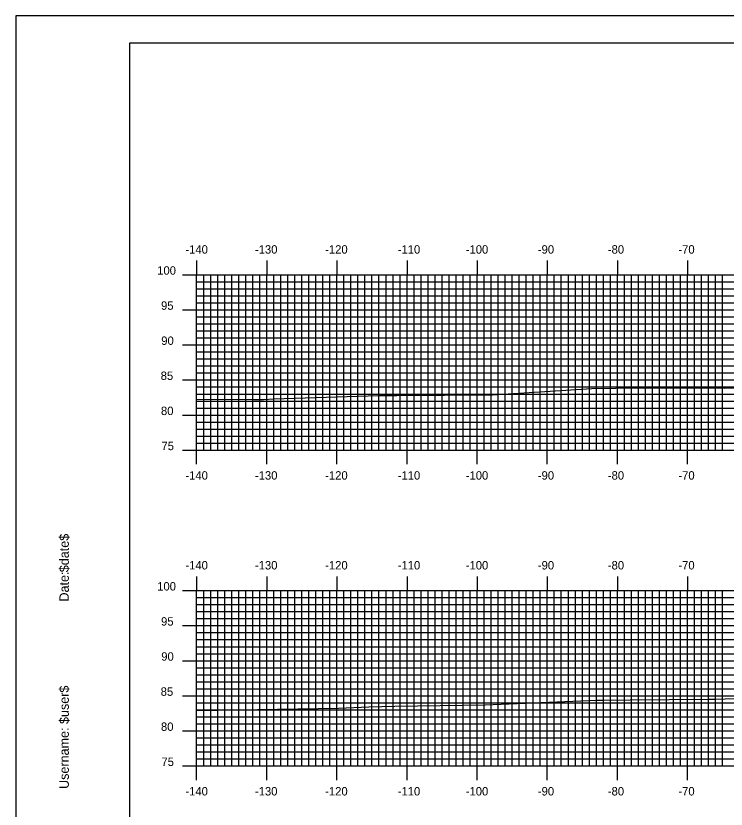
# Model space of a CAD drawing. Extents: x 1666 to 2009, y -1658 to -1438.
# Drawn here: x 1665.9 to 1767.2, y -1550.7 to -1437.7 of the extents above; entities that cross this region are included whole.
import ezdxf

# ---------------------------------------------------------------- set-up
doc = ezdxf.new("R2010")
doc.units = 0
for name, color, linetype in [('BORDER', 7, 'Continuous'), ('H_V ANNOTATION', 7, 'Continuous'), ('MAJOR', 7, 'Continuous'), ('MINOR', 7, 'Continuous'), ('PLOT BOUNDARY', 7, 'Continuous'), ('S_Roadway_Centerline', 7, 'Continuous')]:
    doc.layers.add(name, color=color, linetype=linetype)

msp = doc.modelspace()

# ---------------------------------------------------------------- linework, layer by layer
at = {"layer": 'BORDER'}
msp.add_lwpolyline([(1682.07, -1651.6), (2002.07, -1651.6), (2002.07, -1441.6), (1682.07, -1441.6)], close=True, dxfattribs=at)
at = {"layer": 'MAJOR'}
for p, q in [((1691.67, -1472.6), (1691.67, -1474.6)), ((1701.67, -1472.6), (1701.67, -1474.6)), ((1711.67, -1472.6), (1711.67, -1474.6)), ((1721.67, -1472.6), (1721.67, -1474.6)), ((1731.67, -1472.6), (1731.67, -1474.6)), ((1741.67, -1472.6), (1741.67, -1474.6)), ((1751.67, -1472.6), (1751.67, -1474.6)), ((1761.67, -1472.6), (1761.67, -1474.6)), ((1689.67, -1474.6), (1691.67, -1474.6)), ((1691.67, -1474.6), (1971.67, -1474.6)), ((1691.67, -1499.6), (1691.67, -1474.6)), ((1691.67, -1499.6), (1691.67, -1474.6)), ((1691.67, -1474.6), (1971.67, -1474.6)), ((1701.67, -1499.6), (1701.67, -1474.6)), ((1711.67, -1499.6), (1711.67, -1474.6)), ((1721.67, -1499.6), (1721.67, -1474.6)), ((1731.67, -1499.6), (1731.67, -1474.6)), ((1741.67, -1499.6), (1741.67, -1474.6)), ((1751.67, -1499.6), (1751.67, -1474.6)), ((1761.67, -1499.6), (1761.67, -1474.6)), ((1689.67, -1479.6), (1691.67, -1479.6)), ((1691.67, -1479.6), (1971.67, -1479.6)), ((1689.67, -1484.6), (1691.67, -1484.6)), ((1691.67, -1484.6), (1971.67, -1484.6)), ((1689.67, -1489.6), (1691.67, -1489.6)), ((1691.67, -1489.6), (1971.67, -1489.6)), ((1689.67, -1494.6), (1691.67, -1494.6)), ((1691.67, -1494.6), (1971.67, -1494.6)), ((1689.67, -1499.6), (1691.67, -1499.6)), ((1691.67, -1499.6), (1971.67, -1499.6)), ((1691.67, -1499.6), (1971.67, -1499.6)), ((1691.67, -1501.61), (1691.67, -1499.6)), ((1701.67, -1501.61), (1701.67, -1499.6)), ((1711.67, -1501.61), (1711.67, -1499.6)), ((1721.67, -1501.61), (1721.67, -1499.6)), ((1731.67, -1501.61), (1731.67, -1499.6)), ((1741.67, -1501.61), (1741.67, -1499.6)), ((1751.67, -1501.61), (1751.67, -1499.6)), ((1761.67, -1501.61), (1761.67, -1499.6)), ((1691.67, -1517.6), (1691.67, -1519.6)), ((1701.67, -1517.6), (1701.67, -1519.6)), ((1711.67, -1517.6), (1711.67, -1519.6)), ((1721.67, -1517.6), (1721.67, -1519.6)), ((1731.67, -1517.6), (1731.67, -1519.6)), ((1741.67, -1517.6), (1741.67, -1519.6)), ((1751.67, -1517.6), (1751.67, -1519.6)), ((1761.67, -1517.6), (1761.67, -1519.6)), ((1689.67, -1519.6), (1691.67, -1519.6)), ((1691.67, -1519.6), (1971.67, -1519.6)), ((1691.67, -1544.6), (1691.67, -1519.6)), ((1691.67, -1544.6), (1691.67, -1519.6)), ((1691.67, -1519.6), (1971.67, -1519.6)), ((1701.67, -1544.6), (1701.67, -1519.6)), ((1711.67, -1544.6), (1711.67, -1519.6)), ((1721.67, -1544.6), (1721.67, -1519.6)), ((1731.67, -1544.6), (1731.67, -1519.6)), ((1741.67, -1544.6), (1741.67, -1519.6)), ((1751.67, -1544.6), (1751.67, -1519.6)), ((1761.67, -1544.6), (1761.67, -1519.6)), ((1689.67, -1524.6), (1691.67, -1524.6)), ((1691.67, -1524.6), (1971.67, -1524.6)), ((1689.67, -1529.6), (1691.67, -1529.6)), ((1691.67, -1529.6), (1971.67, -1529.6)), ((1689.67, -1534.6), (1691.67, -1534.6)), ((1691.67, -1534.6), (1971.67, -1534.6)), ((1689.67, -1539.6), (1691.67, -1539.6)), ((1691.67, -1539.6), (1971.67, -1539.6)), ((1689.67, -1544.6), (1691.67, -1544.6)), ((1691.67, -1544.6), (1971.67, -1544.6)), ((1691.67, -1544.6), (1971.67, -1544.6)), ((1691.67, -1546.61), (1691.67, -1544.6)), ((1701.67, -1546.61), (1701.67, -1544.6)), ((1711.67, -1546.61), (1711.67, -1544.6)), ((1721.67, -1546.61), (1721.67, -1544.6)), ((1731.67, -1546.61), (1731.67, -1544.6)), ((1741.67, -1546.61), (1741.67, -1544.6)), ((1751.67, -1546.61), (1751.67, -1544.6)), ((1761.67, -1546.61), (1761.67, -1544.6))]:
    msp.add_line(p, q, dxfattribs=at)
at = {"layer": 'MINOR'}
for p, q in [((1692.67, -1499.6), (1692.67, -1474.6)), ((1693.67, -1499.6), (1693.67, -1474.6)), ((1694.67, -1499.6), (1694.67, -1474.6)), ((1695.67, -1499.6), (1695.67, -1474.6)), ((1696.67, -1499.6), (1696.67, -1474.6)), ((1697.67, -1499.6), (1697.67, -1474.6)), ((1698.67, -1499.6), (1698.67, -1474.6)), ((1699.67, -1499.6), (1699.67, -1474.6)), ((1700.67, -1499.6), (1700.67, -1474.6)), ((1702.67, -1499.6), (1702.67, -1474.6)), ((1703.67, -1499.6), (1703.67, -1474.6)), ((1704.67, -1499.6), (1704.67, -1474.6)), ((1705.67, -1499.6), (1705.67, -1474.6)), ((1706.67, -1499.6), (1706.67, -1474.6)), ((1707.67, -1499.6), (1707.67, -1474.6)), ((1708.67, -1499.6), (1708.67, -1474.6)), ((1709.67, -1499.6), (1709.67, -1474.6)), ((1710.67, -1499.6), (1710.67, -1474.6)), ((1712.67, -1499.6), (1712.67, -1474.6)), ((1713.67, -1499.6), (1713.67, -1474.6)), ((1714.67, -1499.6), (1714.67, -1474.6)), ((1715.67, -1499.6), (1715.67, -1474.6)), ((1716.67, -1499.6), (1716.67, -1474.6)), ((1717.67, -1499.6), (1717.67, -1474.6)), ((1718.67, -1499.6), (1718.67, -1474.6)), ((1719.67, -1499.6), (1719.67, -1474.6)), ((1720.67, -1499.6), (1720.67, -1474.6)), ((1722.67, -1499.6), (1722.67, -1474.6)), ((1723.67, -1499.6), (1723.67, -1474.6)), ((1724.67, -1499.6), (1724.67, -1474.6)), ((1725.67, -1499.6), (1725.67, -1474.6)), ((1726.67, -1499.6), (1726.67, -1474.6)), ((1727.67, -1499.6), (1727.67, -1474.6)), ((1728.67, -1499.6), (1728.67, -1474.6)), ((1729.67, -1499.6), (1729.67, -1474.6)), ((1730.67, -1499.6), (1730.67, -1474.6)), ((1732.67, -1499.6), (1732.67, -1474.6)), ((1733.67, -1499.6), (1733.67, -1474.6)), ((1734.67, -1499.6), (1734.67, -1474.6)), ((1735.67, -1499.6), (1735.67, -1474.6)), ((1736.67, -1499.6), (1736.67, -1474.6)), ((1737.67, -1499.6), (1737.67, -1474.6)), ((1738.67, -1499.6), (1738.67, -1474.6)), ((1739.67, -1499.6), (1739.67, -1474.6)), ((1740.67, -1499.6), (1740.67, -1474.6)), ((1742.67, -1499.6), (1742.67, -1474.6)), ((1743.67, -1499.6), (1743.67, -1474.6)), ((1744.67, -1499.6), (1744.67, -1474.6)), ((1745.67, -1499.6), (1745.67, -1474.6)), ((1746.67, -1499.6), (1746.67, -1474.6)), ((1747.67, -1499.6), (1747.67, -1474.6)), ((1748.67, -1499.6), (1748.67, -1474.6)), ((1749.67, -1499.6), (1749.67, -1474.6)), ((1750.67, -1499.6), (1750.67, -1474.6)), ((1752.67, -1499.6), (1752.67, -1474.6)), ((1753.67, -1499.6), (1753.67, -1474.6)), ((1754.67, -1499.6), (1754.67, -1474.6)), ((1755.67, -1499.6), (1755.67, -1474.6)), ((1756.67, -1499.6), (1756.67, -1474.6)), ((1757.67, -1499.6), (1757.67, -1474.6)), ((1758.67, -1499.6), (1758.67, -1474.6)), ((1759.67, -1499.6), (1759.67, -1474.6)), ((1760.67, -1499.6), (1760.67, -1474.6)), ((1762.67, -1499.6), (1762.67, -1474.6)), ((1763.67, -1499.6), (1763.67, -1474.6)), ((1764.67, -1499.6), (1764.67, -1474.6)), ((1765.67, -1499.6), (1765.67, -1474.6)), ((1766.67, -1499.6), (1766.67, -1474.6)), ((1691.67, -1475.6), (1971.67, -1475.6)), ((1691.67, -1475.6), (1693.68, -1475.6)), ((1691.67, -1476.6), (1971.67, -1476.6)), ((1691.67, -1476.6), (1693.68, -1476.6)), ((1691.67, -1477.6), (1971.67, -1477.6)), ((1691.67, -1477.6), (1693.68, -1477.6)), ((1691.67, -1478.6), (1971.67, -1478.6)), ((1691.67, -1478.6), (1693.68, -1478.6)), ((1691.67, -1480.6), (1971.67, -1480.6)), ((1691.67, -1480.6), (1693.68, -1480.6)), ((1691.67, -1481.6), (1971.67, -1481.6)), ((1691.67, -1481.6), (1693.68, -1481.6)), ((1691.67, -1482.6), (1971.67, -1482.6)), ((1691.67, -1482.6), (1693.68, -1482.6)), ((1691.67, -1483.6), (1971.67, -1483.6)), ((1691.67, -1483.6), (1693.68, -1483.6)), ((1691.67, -1485.6), (1971.67, -1485.6)), ((1691.67, -1485.6), (1693.68, -1485.6)), ((1691.67, -1486.6), (1971.67, -1486.6)), ((1691.67, -1486.6), (1693.68, -1486.6)), ((1691.67, -1487.6), (1971.67, -1487.6)), ((1691.67, -1487.6), (1693.68, -1487.6)), ((1691.67, -1488.6), (1971.67, -1488.6)), ((1691.67, -1488.6), (1693.68, -1488.6)), ((1691.67, -1490.6), (1971.67, -1490.6)), ((1691.67, -1490.6), (1693.68, -1490.6)), ((1691.67, -1491.6), (1971.67, -1491.6)), ((1691.67, -1491.6), (1693.68, -1491.6)), ((1691.67, -1492.6), (1971.67, -1492.6)), ((1691.67, -1492.6), (1693.68, -1492.6)), ((1691.67, -1493.6), (1971.67, -1493.6)), ((1691.67, -1493.6), (1693.68, -1493.6)), ((1691.67, -1495.6), (1971.67, -1495.6)), ((1691.67, -1495.6), (1693.68, -1495.6)), ((1691.67, -1496.6), (1971.67, -1496.6)), ((1691.67, -1496.6), (1693.68, -1496.6)), ((1691.67, -1497.6), (1971.67, -1497.6)), ((1691.67, -1497.6), (1693.68, -1497.6)), ((1691.67, -1498.6), (1971.67, -1498.6)), ((1691.67, -1498.6), (1693.68, -1498.6)), ((1692.67, -1544.6), (1692.67, -1519.6)), ((1693.67, -1544.6), (1693.67, -1519.6)), ((1694.67, -1544.6), (1694.67, -1519.6)), ((1695.67, -1544.6), (1695.67, -1519.6)), ((1696.67, -1544.6), (1696.67, -1519.6)), ((1697.67, -1544.6), (1697.67, -1519.6)), ((1698.67, -1544.6), (1698.67, -1519.6)), ((1699.67, -1544.6), (1699.67, -1519.6)), ((1700.67, -1544.6), (1700.67, -1519.6)), ((1702.67, -1544.6), (1702.67, -1519.6)), ((1703.67, -1544.6), (1703.67, -1519.6)), ((1704.67, -1544.6), (1704.67, -1519.6)), ((1705.67, -1544.6), (1705.67, -1519.6)), ((1706.67, -1544.6), (1706.67, -1519.6)), ((1707.67, -1544.6), (1707.67, -1519.6)), ((1708.67, -1544.6), (1708.67, -1519.6)), ((1709.67, -1544.6), (1709.67, -1519.6)), ((1710.67, -1544.6), (1710.67, -1519.6)), ((1712.67, -1544.6), (1712.67, -1519.6)), ((1713.67, -1544.6), (1713.67, -1519.6)), ((1714.67, -1544.6), (1714.67, -1519.6)), ((1715.67, -1544.6), (1715.67, -1519.6)), ((1716.67, -1544.6), (1716.67, -1519.6)), ((1717.67, -1544.6), (1717.67, -1519.6)), ((1718.67, -1544.6), (1718.67, -1519.6)), ((1719.67, -1544.6), (1719.67, -1519.6)), ((1720.67, -1544.6), (1720.67, -1519.6)), ((1722.67, -1544.6), (1722.67, -1519.6)), ((1723.67, -1544.6), (1723.67, -1519.6)), ((1724.67, -1544.6), (1724.67, -1519.6)), ((1725.67, -1544.6), (1725.67, -1519.6)), ((1726.67, -1544.6), (1726.67, -1519.6)), ((1727.67, -1544.6), (1727.67, -1519.6)), ((1728.67, -1544.6), (1728.67, -1519.6)), ((1729.67, -1544.6), (1729.67, -1519.6)), ((1730.67, -1544.6), (1730.67, -1519.6)), ((1732.67, -1544.6), (1732.67, -1519.6)), ((1733.67, -1544.6), (1733.67, -1519.6)), ((1734.67, -1544.6), (1734.67, -1519.6)), ((1735.67, -1544.6), (1735.67, -1519.6)), ((1736.67, -1544.6), (1736.67, -1519.6)), ((1737.67, -1544.6), (1737.67, -1519.6)), ((1738.67, -1544.6), (1738.67, -1519.6)), ((1739.67, -1544.6), (1739.67, -1519.6)), ((1740.67, -1544.6), (1740.67, -1519.6)), ((1742.67, -1544.6), (1742.67, -1519.6)), ((1743.67, -1544.6), (1743.67, -1519.6)), ((1744.67, -1544.6), (1744.67, -1519.6)), ((1745.67, -1544.6), (1745.67, -1519.6)), ((1746.67, -1544.6), (1746.67, -1519.6)), ((1747.67, -1544.6), (1747.67, -1519.6)), ((1748.67, -1544.6), (1748.67, -1519.6)), ((1749.67, -1544.6), (1749.67, -1519.6)), ((1750.67, -1544.6), (1750.67, -1519.6)), ((1752.67, -1544.6), (1752.67, -1519.6)), ((1753.67, -1544.6), (1753.67, -1519.6)), ((1754.67, -1544.6), (1754.67, -1519.6)), ((1755.67, -1544.6), (1755.67, -1519.6)), ((1756.67, -1544.6), (1756.67, -1519.6)), ((1757.67, -1544.6), (1757.67, -1519.6)), ((1758.67, -1544.6), (1758.67, -1519.6)), ((1759.67, -1544.6), (1759.67, -1519.6)), ((1760.67, -1544.6), (1760.67, -1519.6)), ((1762.67, -1544.6), (1762.67, -1519.6)), ((1763.67, -1544.6), (1763.67, -1519.6)), ((1764.67, -1544.6), (1764.67, -1519.6)), ((1765.67, -1544.6), (1765.67, -1519.6)), ((1766.67, -1544.6), (1766.67, -1519.6)), ((1691.67, -1520.6), (1971.67, -1520.6)), ((1691.67, -1520.6), (1693.68, -1520.6)), ((1691.67, -1521.6), (1971.67, -1521.6)), ((1691.67, -1521.6), (1693.68, -1521.6)), ((1691.67, -1522.6), (1971.67, -1522.6)), ((1691.67, -1522.6), (1693.68, -1522.6)), ((1691.67, -1523.6), (1971.67, -1523.6)), ((1691.67, -1523.6), (1693.68, -1523.6)), ((1691.67, -1525.6), (1971.67, -1525.6)), ((1691.67, -1525.6), (1693.68, -1525.6)), ((1691.67, -1526.6), (1971.67, -1526.6)), ((1691.67, -1526.6), (1693.68, -1526.6)), ((1691.67, -1527.6), (1971.67, -1527.6)), ((1691.67, -1527.6), (1693.68, -1527.6)), ((1691.67, -1528.6), (1971.67, -1528.6)), ((1691.67, -1528.6), (1693.68, -1528.6)), ((1691.67, -1530.6), (1971.67, -1530.6)), ((1691.67, -1530.6), (1693.68, -1530.6)), ((1691.67, -1531.6), (1971.67, -1531.6)), ((1691.67, -1531.6), (1693.68, -1531.6)), ((1691.67, -1532.6), (1971.67, -1532.6)), ((1691.67, -1532.6), (1693.68, -1532.6)), ((1691.67, -1533.6), (1971.67, -1533.6)), ((1691.67, -1533.6), (1693.68, -1533.6)), ((1691.67, -1535.6), (1971.67, -1535.6)), ((1691.67, -1535.6), (1693.68, -1535.6)), ((1691.67, -1536.6), (1971.67, -1536.6)), ((1691.67, -1536.6), (1693.68, -1536.6)), ((1691.67, -1537.6), (1971.67, -1537.6)), ((1691.67, -1537.6), (1693.68, -1537.6)), ((1691.67, -1538.6), (1971.67, -1538.6)), ((1691.67, -1538.6), (1693.68, -1538.6)), ((1691.67, -1540.6), (1971.67, -1540.6)), ((1691.67, -1540.6), (1693.68, -1540.6)), ((1691.67, -1541.6), (1971.67, -1541.6)), ((1691.67, -1541.6), (1693.68, -1541.6)), ((1691.67, -1542.6), (1971.67, -1542.6)), ((1691.67, -1542.6), (1693.68, -1542.6)), ((1691.67, -1543.6), (1971.67, -1543.6)), ((1691.67, -1543.6), (1693.68, -1543.6))]:
    msp.add_line(p, q, dxfattribs=at)
at = {"layer": 'PLOT BOUNDARY'}
msp.add_lwpolyline([(1665.89, -1657.72), (2005.89, -1657.72), (2005.89, -1437.72), (1665.89, -1437.72)], close=True, dxfattribs=at)
at = {"layer": 'S_Roadway_Centerline'}
for points in [[(1691.67, -1492.34), (1699.81, -1492.38), (1701.19, -1492.36), (1702.67, -1492.28), (1717.58, -1491.83), (1720.22, -1491.81), (1733.87, -1491.74), (1748.02, -1490.83), (1751.46, -1490.79), (1754.73, -1490.74), (1766.98, -1490.75), (1771.61, -1490.61), (1783.49, -1489.99), (1789.56, -1489.78), (1809.24, -1489.53), (1816.75, -1489.54), (1824.44, -1489.13), (1833.5, -1489.1), (1841.83, -1489.15), (1848.09, -1488.88), (1855.96, -1488.91), (1865.49, -1488.85), (1876.3, -1488.74)], [(1691.67, -1536.67), (1711.89, -1536.34), (1716.2, -1536.19), (1719.95, -1536.08), (1732.83, -1535.88), (1748.72, -1535.24), (1749.56, -1535.21), (1753.49, -1535.18), (1764.64, -1535.1), (1765.63, -1535.07), (1779.94, -1534.59), (1782.5, -1534.5), (1785.63, -1534.41), (1798.54, -1534.19), (1803.32, -1534.13), (1815.26, -1533.72), (1824.65, -1533.57), (1831.43, -1533.46), (1839.32, -1533.42), (1847.88, -1533.28), (1858.32, -1532.95), (1864.78, -1532.81), (1875.82, -1532.7)]]:
    msp.add_lwpolyline(points, dxfattribs=at)

# ---------------------------------------------------------------- texts
at = {"layer": 'BORDER'}
for s, p in [('$date$', (1673.44, -1516.99)), ('Date:', (1673.44, -1521.17)), ('$user$', (1673.44, -1538.62)), ('Username:', (1673.44, -1547.87))]:
    msp.add_text(s, height=1.339, rotation=90, dxfattribs=at).set_placement(p)
at = {"layer": 'H_V ANNOTATION'}
for s, p in [('-140', (1690.06, -1471.6)), ('-130', (1699.98, -1471.6)), ('-120', (1709.99, -1471.6)), ('-110', (1720.34, -1471.6)), ('-100', (1730.04, -1471.6)), ('-90', (1740.32, -1471.6)), ('-80', (1750.3, -1471.6)), ('-70', (1760.36, -1471.6)), ('100', (1686.04, -1474.6)), ('95', (1686.59, -1479.6)), ('90', (1686.62, -1484.6)), ('85', (1686.54, -1489.6)), ('80', (1686.58, -1494.6)), ('75', (1686.65, -1499.6)), ('-140', (1690.06, -1503.8)), ('-130', (1699.98, -1503.8)), ('-120', (1709.99, -1503.8)), ('-110', (1720.34, -1503.8)), ('-100', (1730.04, -1503.8)), ('-90', (1740.32, -1503.8)), ('-80', (1750.3, -1503.8)), ('-70', (1760.36, -1503.8)), ('-140', (1690.06, -1516.6)), ('-130', (1699.98, -1516.6)), ('-120', (1709.99, -1516.6)), ('-110', (1720.34, -1516.6)), ('-100', (1730.04, -1516.6)), ('-90', (1740.32, -1516.6)), ('-80', (1750.3, -1516.6)), ('-70', (1760.36, -1516.6)), ('100', (1686.04, -1519.6)), ('95', (1686.59, -1524.6)), ('90', (1686.62, -1529.6)), ('85', (1686.54, -1534.6)), ('80', (1686.58, -1539.6)), ('75', (1686.65, -1544.6)), ('-140', (1690.06, -1548.8)), ('-130', (1699.98, -1548.8)), ('-120', (1709.99, -1548.8)), ('-110', (1720.34, -1548.8)), ('-100', (1730.04, -1548.8)), ('-90', (1740.32, -1548.8)), ('-80', (1750.3, -1548.8)), ('-70', (1760.36, -1548.8))]:
    msp.add_text(s, height=1.2, dxfattribs=at).set_placement(p)
at = {"layer": 'MAJOR'}
for p in [(1691.66, -1499.6), (1691.66, -1544.6)]:
    msp.add_text('-', height=0.012, dxfattribs=at).set_placement(p)

doc.saveas('drawing.dxf')
